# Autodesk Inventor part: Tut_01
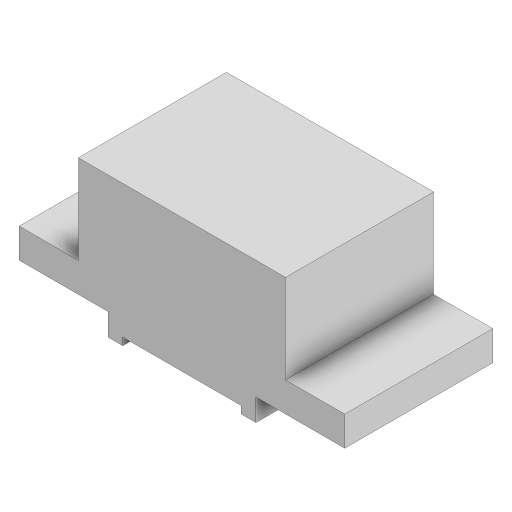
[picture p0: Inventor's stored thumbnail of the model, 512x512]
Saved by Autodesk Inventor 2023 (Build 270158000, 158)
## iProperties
Created: 2022-07
Part Number: Tut_01
Material: Generic
Document SubType Name: Modeling
Designer: LENOVO-CADCIM
Density: 1 g/cm^3
Appearance: Default
Author: LENOVO-CADCIM
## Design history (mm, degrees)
sketch "Sketch1"
  geometry: L1 (0, 0)-(2, 0); L2 (2, 0)-(2, -0.25); L3 (2, -0.25)-(2.5, -0.25); L4 (2.5, -0.25)-(2.5, 0.5); L5 (2.5, 0.5)-(5.5, 0.5); L6 (5.5, 0.5)-(5.5, 1.5); L7 (-2, 0)-(0, 0); L8 (5.5, 1.5)-(3.5, 1.5); L9 (3.5, 1.5)-(3.5, 4.5); L10 (3.5, 4.5)-(-3.5, 4.5); L11 (-3.5, 4.5)-(-3.5, 1.5); L12 (-3.5, 1.5)-(-5.5, 1.5); L13 (-5.5, 1.5)-(-5.5, 0.5); L14 (-5.5, 0.5)-(-2.5, 0.5); L15 (-2.5, 0.5)-(-2.5, -0.25); L16 (-2.5, -0.25)-(-2, -0.25); L17 (-2, -0.25)-(-2, 0)
  constraints: 34 end point, 10 perpendicular, 4 horizontal, 2 vertical, 1 point on line
  dimensions: "d0" = 2 distance of L1.start L1.end; "d2" = 0.25 distance of L1.end L2.end; "d3" = 0.5 distance of L2.end L3.end; "d4" = 0.75 distance of L3.end L4.end; "d5" = 3 distance of L4.end L5.end; "d6" = 1 distance of L5.end L6.end; "d8" = 2 distance of L6.end L8.end; "d9" = 3 distance of L8.end L9.end; "d10" = 7 distance of L9.end L10.end; "d11" = 3 distance of L10.end L11.end; "d18" = 2 distance of L11.end L12.end; "d19" = 1 distance of L12.end L13.end; "d20" = 3 distance of L13.end L14.end; "d21" = 0.75 distance of L14.end L15.end; "d26" = 0.5 distance of L15.end L16.end
extrude "Extrusion1" new body sketch "Sketch1" distance "d27" = 5; taper "d28" = 0 deg
body "Solid1"
